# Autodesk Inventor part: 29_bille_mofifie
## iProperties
Created: 2002-11
Part Number: 29_bille_mofifie
Material: Par défaut
Document SubType Name: Modélisation
Designer: poste-2
Control State: 0
Master: False
Checked Out: False
Shininess: 21.0
Length Units: 11269
Angle Units: 11279
Time Units: 11290
Mass Units: 11283
Length Display Precision: 3
Angle Display Precision: 2
Compacted: True
Density: 0.0
Volumn: 0.0
Area: 0.0
PropertySet Name: Model Information
Author: poste-2
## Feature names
1. Révolution1 [Revolution]
